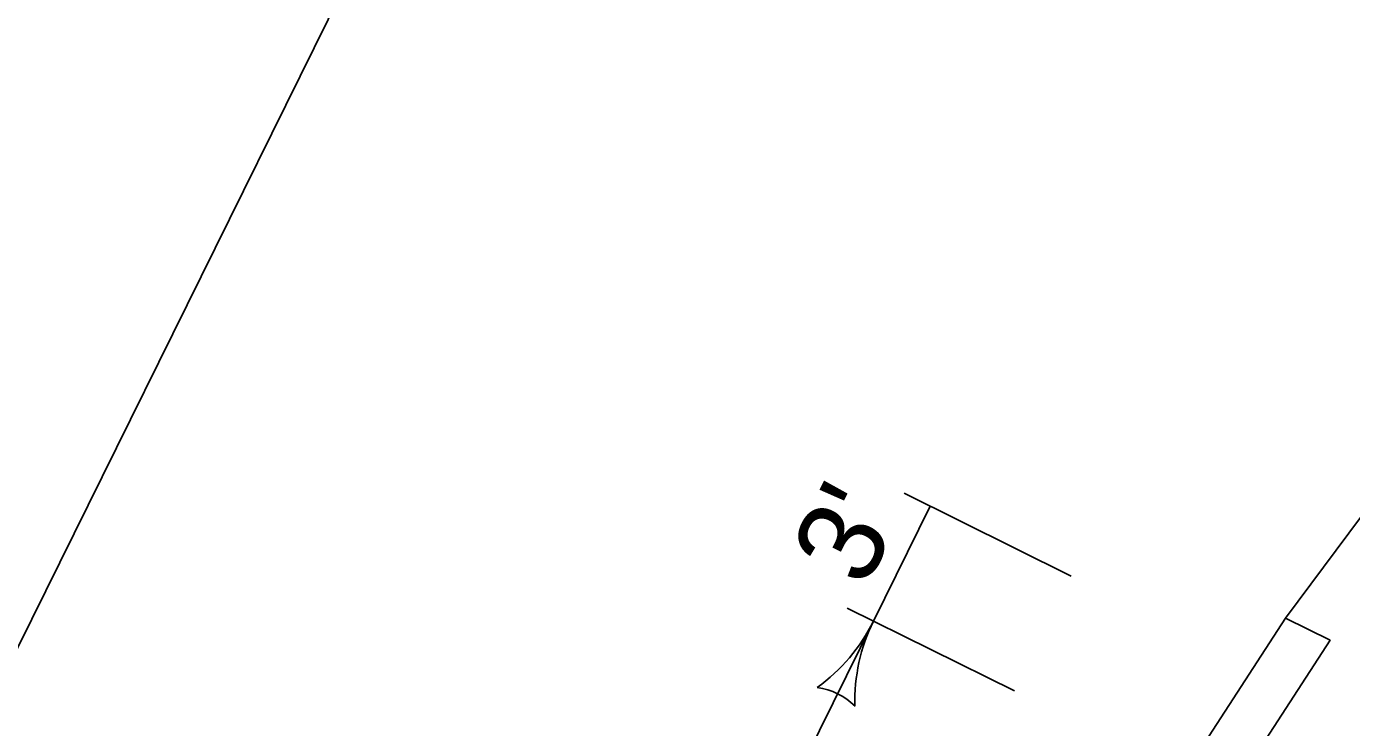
# Model space of a CAD drawing. Extents: x 14104283 to 14128447, y 8633203 to 8671666.
# Drawn here: x 14118261.4 to 14118385.5, y 8668759.2 to 8668824.8 of the extents above; entities that cross this region are included whole.
import ezdxf

# ---------------------------------------------------------------- set-up
doc = ezdxf.new("R2010")
doc.units = 0
for name, color, linetype in [('dsnCellElements', 7, 'Continuous'), ('dsnTextFinalPlan', 7, 'Continuous'), ('dsnTextOverlapEven', 7, 'Continuous'), ('TC_SubstrataExistingPavement', 7, 'Continuous'), ('Terrain', 7, 'Continuous')]:
    doc.layers.add(name, color=color, linetype=linetype)

# ---------------------------------------------------------------- blocks, each defined once
blk = doc.blocks.new('LT')
at = {"layer": 'dsnCellElements'}
for centre, radius, start, end in [((-3.564, 0), 1.642, 342.2666, 17.7333), ((0, 4.25), 4.25, 241.9275, 270), ((0, -4.25), 4.25, 90, 118.0725)]:
    blk.add_arc(centre, radius, start, end, dxfattribs=at)

msp = doc.modelspace()

# ---------------------------------------------------------------- linework, layer by layer
at = {"layer": 'dsnTextFinalPlan'}
for p, q in [((14118343.62, 8668781.13), (14118359.28, 8668773.39)), ((14118340.75, 8668769.16), (14118346.07, 8668779.92)), ((14118338.3, 8668770.37), (14118353.96, 8668762.63)), ((14118319.48, 8668726.13), (14118340.75, 8668769.16))]:
    msp.add_line(p, q, dxfattribs=at)
msp.add_lwpolyline([(14117870.36, 8667977.42), (14118384.92, 8669018.16), (14118565.56, 8668928.85), (14118050.99, 8667888.12)], close=True, dxfattribs=at)
at = {"layer": 'dsnTextOverlapEven'}
msp.add_lwpolyline([(14117870.36, 8667977.42), (14118384.92, 8669018.16), (14118565.56, 8668928.85), (14118050.99, 8667888.12)], close=True, dxfattribs=at)
at = {"layer": 'TC_SubstrataExistingPavement'}
msp.add_lwpolyline([(14118359.1, 8668736.38), (14118363.29, 8668734.31), (14118375.98, 8668755.74), (14118383.52, 8668767.37), (14118379.34, 8668769.44)], dxfattribs=at)
at = {"layer": 'Terrain'}
msp.add_lwpolyline([(14118312.3, 8668644.82), (14118315.38, 8668650.41), (14118318.4, 8668656.85), (14118336.09, 8668694.53), (14118351.32, 8668721.95), (14118359.1, 8668736.38), (14118371.8, 8668757.81), (14118379.34, 8668769.44), (14118400.6, 8668797.95), (14118408.04, 8668806.8), (14118456.58, 8668898.64)], dxfattribs=at)

# ---------------------------------------------------------------- block references
at = {"layer": 'dsnTextFinalPlan', "xscale": 3.942400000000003, "yscale": 3.9424000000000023, "rotation": 63.69110745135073}
msp.add_blockref('LT', (14118340.75, 8668769.16), dxfattribs=at)

# ---------------------------------------------------------------- texts
at = {"layer": 'dsnTextFinalPlan'}
msp.add_text("3'", height=8, rotation=63.6911, dxfattribs=at).set_placement((14118339.99, 8668772.1))

doc.saveas('drawing.dxf')
